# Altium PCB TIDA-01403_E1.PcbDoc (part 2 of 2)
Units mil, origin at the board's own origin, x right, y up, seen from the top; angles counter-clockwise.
Board outline 4150 x 3450 mil, 4 copper layers (Top Layer, GND, PWR, Bottom Layer), stack 61.6 mil thick; 155 components, 99 nets, 498 pads, 229 vias.
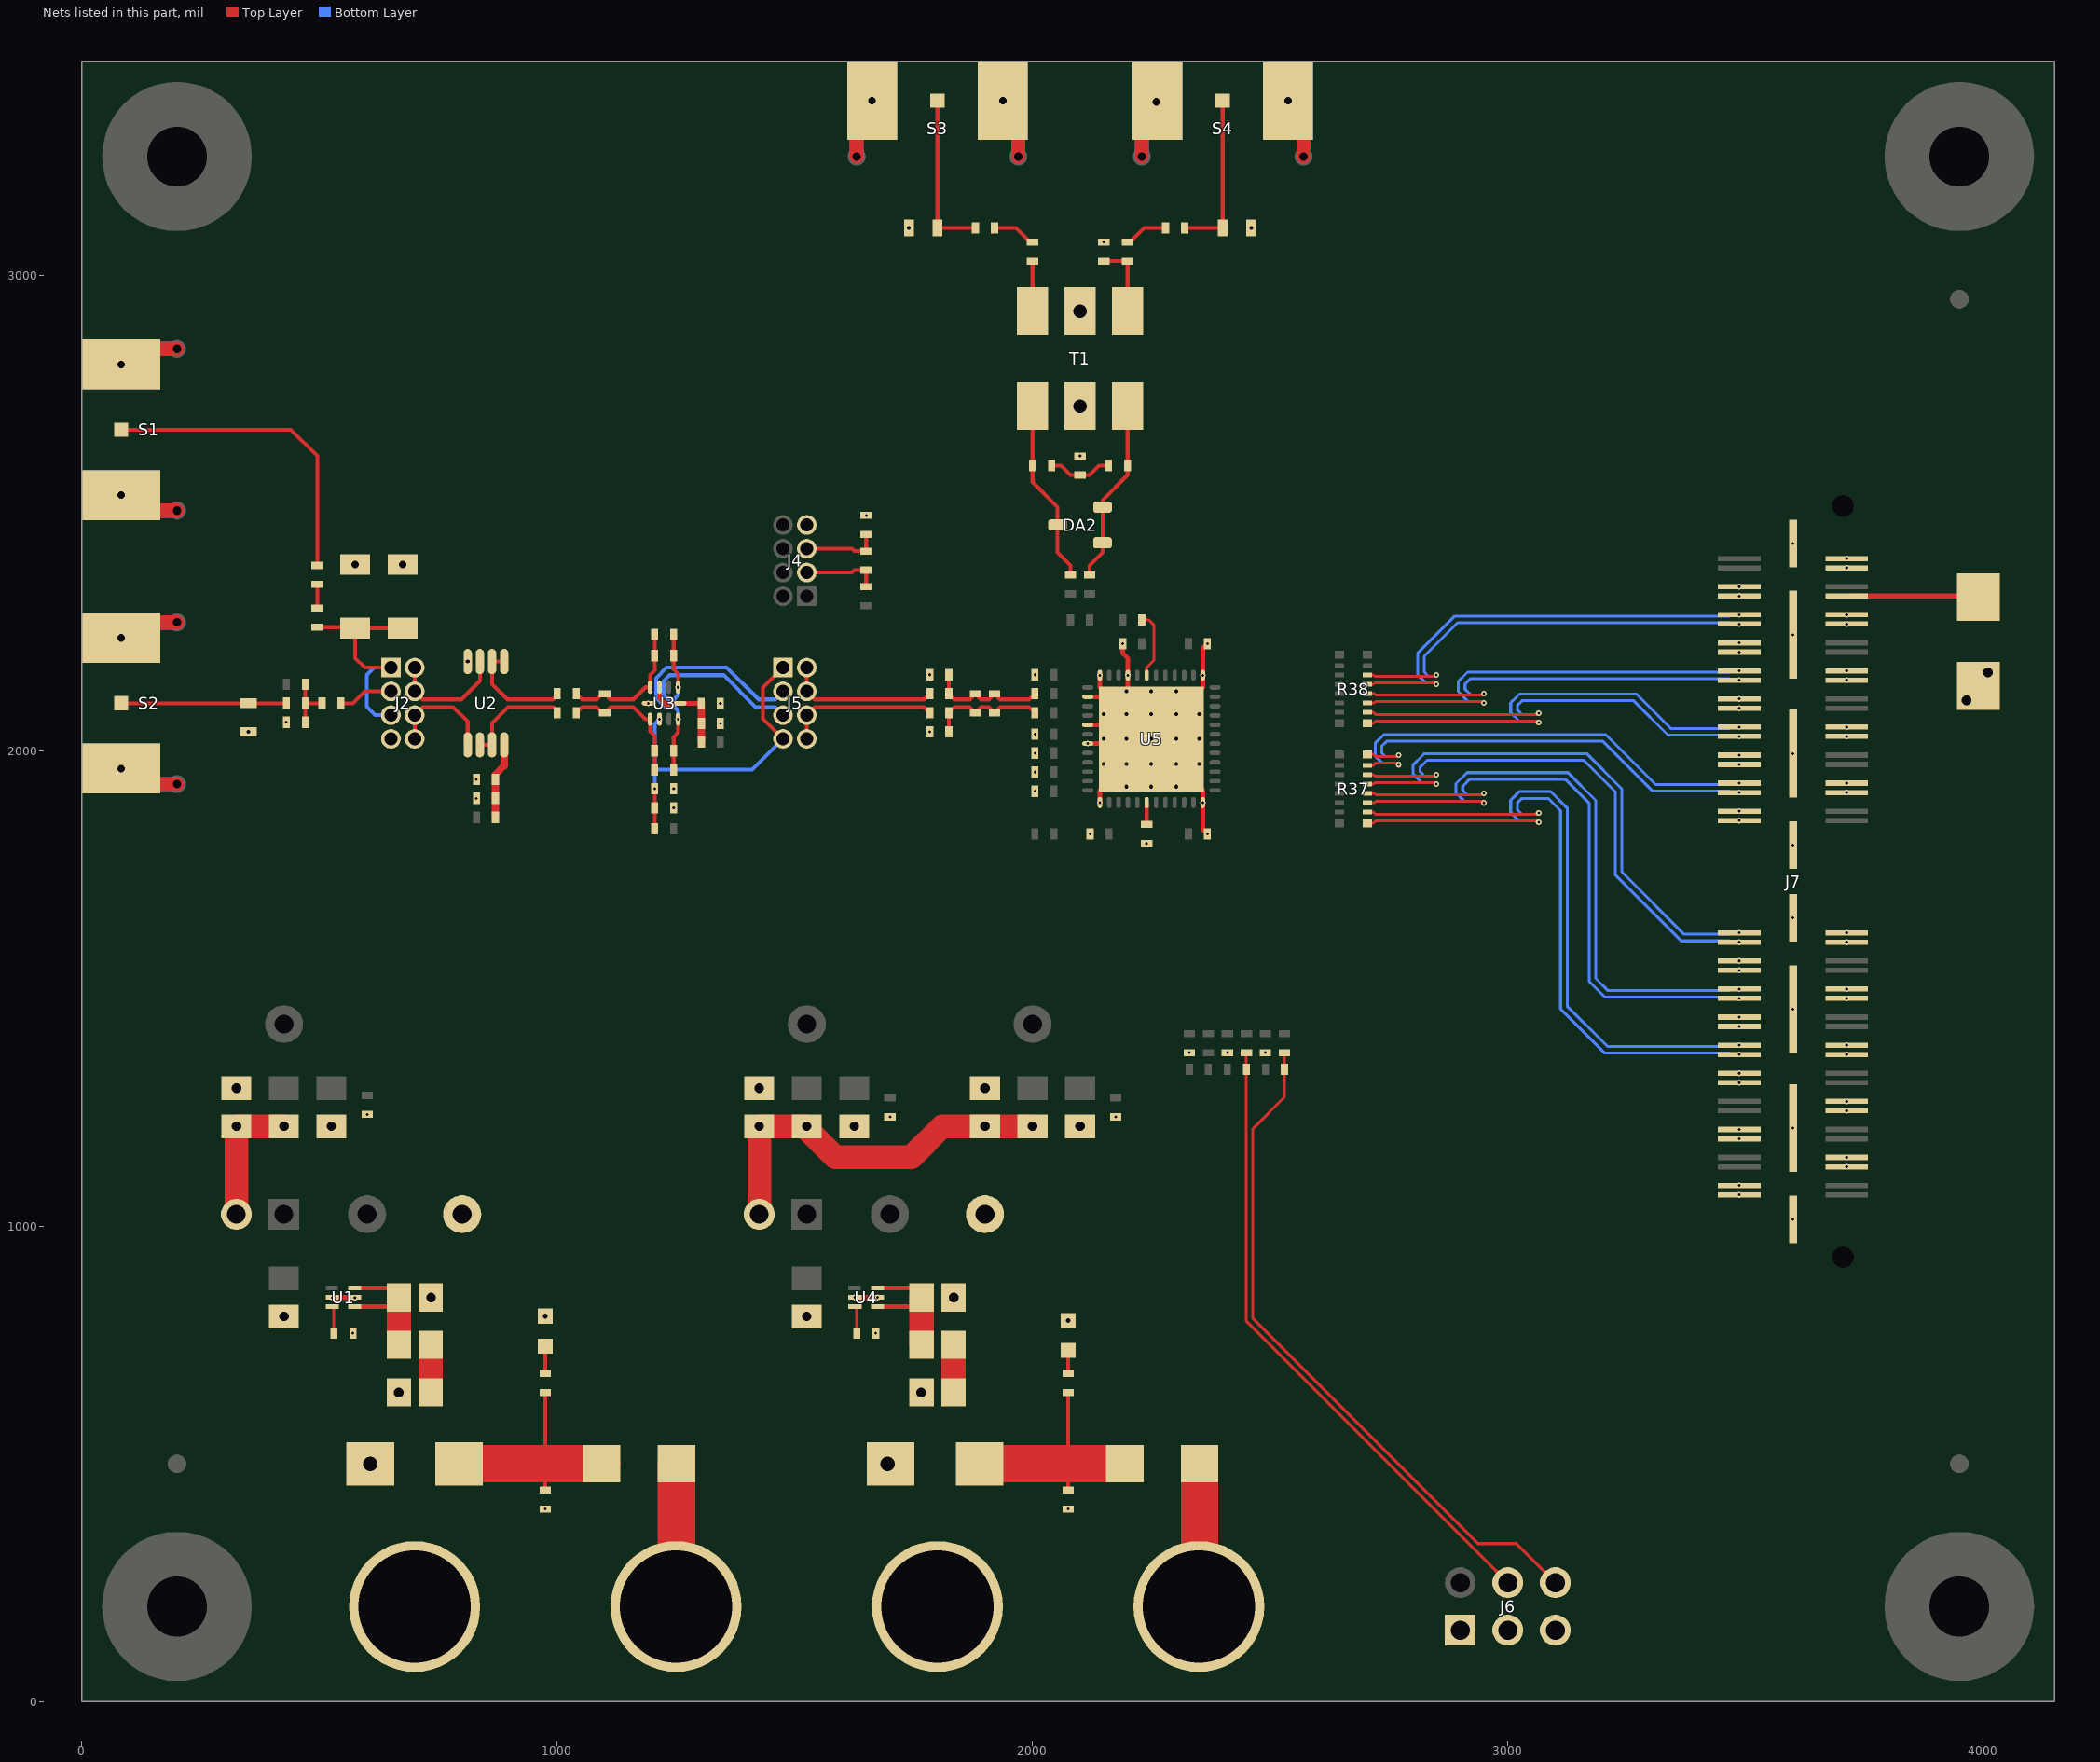
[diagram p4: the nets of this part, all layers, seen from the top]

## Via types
v1: diameter 12, hole 6, Top Layer to Bottom Layer, 153 vias
v2: diameter 40, hole 20, Top Layer to Bottom Layer, 35 vias
v3: diameter 19.68, hole 7.87, Top Layer to Bottom Layer, 21 vias
v4: diameter 32, hole 16, Top Layer to Bottom Layer, 10 vias
v5: diameter 16, hole 8, Top Layer to Bottom Layer, 4 vias
v6: diameter 56, hole 28, Top Layer to Bottom Layer, 2 vias
v7: diameter 60, hole 30, Top Layer to Bottom Layer, 2 vias
v8: diameter 20, hole 10, Top Layer to Bottom Layer, 2 vias

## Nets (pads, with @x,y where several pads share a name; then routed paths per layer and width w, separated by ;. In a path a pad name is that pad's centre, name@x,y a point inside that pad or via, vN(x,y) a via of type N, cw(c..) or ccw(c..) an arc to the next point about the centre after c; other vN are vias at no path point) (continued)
D0_D1_N: J7.57 R37.9 | length 1413
  Top Layer w6: R37.9@2704.53,1847.66 2717.37,1847.66 2721.94,1852.22 3062,1852.22 v1(3065,1849.22)
  Bottom Layer w6: v1(3065,1849.22) 3062,1852.22 3024.2,1852.22 3006,1870.42 3006,1896 3024,1914 3090.8,1914 3125,1879.8 3125,1462.83 3210,1377.83 3372,1377.83 3465.66,1377.83 3468.5,1380.67 v1(3487.01,1380.67)
D0_D1_P: J7.59 R37.10 | length 1366.6
  Top Layer w6: R37.10@2704.53,1870.79 2717.37,1870.79 2721.93,1866.22 3062,1866.22 v1(3065,1869.22)
  Bottom Layer w6: v1(3065,1869.22) 3062,1866.22 3030,1866.22 3020,1876.22 3020,1890.2 3029.8,1900 3085,1900 3111,1874 3111,1457.03 3204.2,1363.83 3465.66,1363.83 3468.5,1360.98 v1(3487.01,1360.98)
D2_D3_N: J7.49 R37.11 | length 1349.1
  Top Layer w6: R37.11@2706.48,1890.47 2719.32,1890.47 2722.16,1893.32 2947,1893.32 v1(2950,1890.32)
  Bottom Layer w6: v1(2950,1890.32) 2947,1893.32 2909.2,1893.32 2891,1911.52 2891,1930.8 2914.2,1954 3126.8,1954 3185,1895.8 3185,1520.94 3210,1495.94 3372,1495.94 3465.66,1495.94 3468.5,1498.78 v1(3487.01,1498.78)
D2_D3_P: J7.51 R37.12 | length 1302.7
  Top Layer w6: R37.12@2706.48,1910.16 2719.32,1910.16 2722.16,1907.32 2947,1907.32 v1(2950,1910.32)
  Bottom Layer w6: v1(2950,1910.32) 2947,1907.32 2915,1907.32 2905,1917.32 2905,1925 2920,1940 3121,1940 3171,1890 3171,1515.14 3204.2,1481.94 3465.66,1481.94 3468.5,1479.09 v1(3487.01,1479.09)
D4_D5_N: J7.41 R37.13 | length 1182.3
  Top Layer w6: R37.13@2704.53,1929.84 2717.37,1929.84 2720.21,1932.68 2847,1932.68 v1(2850,1929.68)
  Bottom Layer w6: v1(2850,1929.68) 2847,1932.68 2819.2,1932.68 2801,1950.89 2801,1970.8 2820.1,1989.9 2824.2,1994 3166,1994 3240,1920 3240,1745 3370.95,1614.05 3465.66,1614.05 3468.5,1616.89 v1(3487.01,1616.89)
D4_D5_P: J7.43 R37.14 | length 1135.9
  Top Layer w6: R37.14@2704.53,1949.53 2717.37,1949.53 2720.21,1946.68 2847,1946.68 v1(2850,1949.68)
  Bottom Layer w6: v1(2850,1949.68) 2847,1946.68 2825,1946.68 2815,1956.68 2815,1965 2830,1980 3160.2,1980 3226,1914.2 3226,1739.2 3365.15,1600.05 3465.66,1600.05 3468.5,1597.2 v1(3487.01,1597.2)
D6_D7_N: J7.33 R37.15 | length 970
  Top Layer w6: R37.15@2704.53,1969.21 2717.37,1969.21 2721.94,1973.78 2767,1973.78 v1(2770,1970.78)
  Bottom Layer w6: v1(2770,1970.78) 2767,1973.78 2736.42,1973.78 2721,1989.2 2721,2015.8 2739.2,2034 3205.8,2034 3310.79,1929.01 3465.66,1929.01 3468.5,1931.85 v1(3487.01,1931.85)
D6_D7_P: J7.35 R37.16 | length 923.7
  Top Layer w6: R37.16@2704.53,1992.34 2717.37,1992.34 2721.93,1987.78 2767,1987.78 v1(2770,1990.78)
  Bottom Layer w6: v1(2770,1990.78) 2767,1987.78 2742.22,1987.78 2735,1995 2735,2010 2745,2020 3200,2020 3304.99,1915.01 3465.66,1915.01 3468.5,1912.17 v1(3487.01,1912.17)
D8_D9_N: J7.25 R38.9 | length 971.3
  Top Layer w6: R38.9@2704.53,2057.66 2717.37,2057.66 2721.94,2062.22 3062,2062.22 v1(3065,2059.22)
  Bottom Layer w6: v1(3065,2059.22) 3062,2062.22 3024.2,2062.22 3006,2080.42 3006,2100.8 3010.1,2104.9 3014.2,2109 3024.3,2119.1 3270.9,2119.1 3342.88,2047.12 3465.66,2047.12 3468.5,2049.96 v1(3487.01,2049.96)
D8_D9_P: J7.27 R38.10 | length 925
  Top Layer w6: R38.10@2704.53,2080.79 2717.37,2080.79 2721.93,2076.22 3062,2076.22 v1(3065,2079.22)
  Bottom Layer w6: v1(3065,2079.22) 3062,2076.22 3030,2076.22 3020,2086.22 3020,2095 3030.1,2105.1 3265.1,2105.1 3337.08,2033.12 3465.66,2033.12 3468.5,2030.28 v1(3487.01,2030.28)
D10_D11_N: J7.17 R38.11 | length 931.9
  Top Layer w6: R38.11@2706.48,2100.47 2719.32,2100.47 2722.16,2103.32 2947,2103.32 v1(2950,2100.32)
  Bottom Layer w6: v1(2950,2100.32) 2947,2103.32 2916.68,2103.32 2896,2124 2896,2146 2915.23,2165.23 3372,2165.23 3465.66,2165.23 3468.5,2168.07 v1(3487.01,2168.07)
D10_D11_P: J7.19 R38.12 | length 885.5
  Top Layer w6: R38.12@2706.48,2120.16 2719.32,2120.16 2722.16,2117.32 2947,2117.32 v1(2950,2120.32)
  Bottom Layer w6: v1(2950,2120.32) 2947,2117.32 2922.48,2117.32 2910,2129.8 2910,2140.2 2921.03,2151.23 3465.66,2151.23 3468.5,2148.39 v1(3487.01,2148.39)
D12_D13_N: J7.9 R38.13 | length 951.8
  Top Layer w6: R38.13@2704.53,2139.84 2717.37,2139.84 2720.21,2142.68 2847,2142.68 v1(2850,2139.68)
  Bottom Layer w6: v1(2850,2139.68) 2847,2142.68 2827.32,2142.68 2810,2160 2810,2204.8 2888.54,2283.34 3465.66,2283.34 3468.5,2286.18 v1(3487.01,2286.18)
D12_D13_P: J7.11 R38.14 | length 905.4
  Top Layer w6: R38.14@2704.53,2159.53 2717.37,2159.53 2720.21,2156.68 2847,2156.68 v1(2850,2159.68)
  Bottom Layer w6: v1(2850,2159.68) 2847,2156.68 2833.11,2156.68 2824,2165.8 2824,2199 2894.34,2269.34 3465.66,2269.34 3468.5,2266.5 v1(3487.01,2266.5)
EXT_VIN1: C7.1 C9.1 C14.1 DA1.1 L3.1 R6.1 | length 604.8
  Top Layer w8: C14.1@975,445 975,500 R6.1@975,650
  Top Layer w51.18: C9.1@733.46,650 L3.1@733.46,750
  Top Layer w78.74: C7.1@793.5,500 975,500 DA1.1@1093.26,500
EXT_VIN2: C28.1 C31.1 C41.1 DA3.1 L7.1 R23.1 | length 604.8
  Top Layer w8: C41.1@2075,445 R23.1@2075,650
  Top Layer w51.18: C31.1@1833.46,650 L7.1@1833.46,750
  Top Layer w78.74: C28.1@1892.76,500 2074.26,500 DA3.1@2192.52,500
FDA_VCC: C20.1 C21.1 L5.2 U3.3 U3.10 | length 197.1
  Top Layer w10: U3.3@1215.16,2133.47 1215.16,2110.58 1225.73,2100 U3.10@1258.47,2100 1302.79,2100 C20.1@1303,2099.79
  Top Layer w15: C20.1@1303,2099.79 1303.16,2099.63 C21.1@1303.16,2057.73 1303.16,2018.08 L5.2@1303.24,2018
FDA_VIN_N: C15.1 C18.2 R7.2 R10.1 U3.6 | length 291.4
  Top Layer w8: R7.2@1040,2080 1052,2092 1083,2092 1095,2080 C15.1@1100,2080 1112,2092 1160,2092 1185.46,2066.54 U3.6@1195.47,2066.54 1195.47,2040.53 1205,2031 C18.2@1205,2000 R10.1@1205,1960
FDA_VIN_P: C15.2 C19.2 R8.2 R11.1 U3.4 | length 287.1
  Top Layer w8: R8.2@1040,2120 1052,2108 1083,2108 1095,2120 C15.2@1100,2120 1112,2108 1160,2108 1185.47,2133.47 U3.4@1195.47,2133.47 ; U3.4@1195,2133.94 U3.4@1195.47,2133.47 ; R11.1@1205,2235 C19.2@1205,2200 1205,2169 1195.47,2159.48 U3.4@1195.47,2133.47
FDA_VOCM: C16.1 C17.1 J5.1 J5.7 R9.1 U3.7 | length 726.6
  Top Layer w8: v1(1205,1920) C16.1@1205,1880 1205,1836.12 R9.1@1205.32,1835.81 ; J5.7@1475,2025 1433.09,2066.91 1433.09,2133.09 J5.1@1475,2175
  Bottom Layer w8: v1(1205,1920) 1205,1960 ; v1(1215.16,2066.54) 1205,2056.38 1205,1960 ; J5.7@1475,2034.87 J5.7@1475,2025 1410,1960 1205,1960
FDAOUT_N: C19.1 J5.5 R11.2 U3.1 | length 479.6
  Top Layer w8: R11.2@1245,2235 C19.1@1245,2200 1245,2171 1254.53,2161.47 v1(1254.53,2133.47)
  Bottom Layer w8: v1(1254.53,2133.47) 1254.53,2117.53 1245,2108 1233.63,2108 1224,2117.63 1224,2146.37 1236.63,2159 1350,2159 1417,2092 1458,2092 J5.5@1475,2075
FDAOUT_P: C18.1 J5.3 R10.2 U3.9 | length 538.8
  Top Layer w8: R10.2@1245,1960 C18.1@1245,2000 1245,2029 1254.53,2038.53 v1(1254.53,2066.54)
  Bottom Layer w8: v1(1254.53,2066.54) 1254.53,2084.47 1247,2092 1227,2092 1208,2111 1208,2153 1230,2175 1356.63,2175 1423.63,2108 1458,2108 J5.3@1475,2125
FILIN_N: J5.6 J5.8 R12.1 | length 321
  Top Layer w8: J5.8@1525,2025 J5.6@1525,2075 1542,2092 1772,2092 R12.1@1784,2080
FILIN_P: J5.2 J5.4 R13.1 | length 321
  Top Layer w8: J5.2@1525,2175 J5.4@1525,2125 1542,2108 1772,2108 R13.1@1784,2120
FILOUT_N: C26.1 C35.2 R12.2 R18.1 R21.1 | length 250.9
  Top Layer w8: C26.1@1824,2040 R12.2@1824,2080 1836,2092 1868.21,2092 R18.1@1880,2080.21 ; R18.1@1879.9,2080.11 R18.1@1880,2080 1892,2092 1908,2092 C35.2@1920,2080 1932,2092 1955,2092 1985,2092 1993,2092 R21.1@2005,2080
FILOUT_P: C27.1 C35.1 R13.2 R18.2 R22.1 | length 250.9
  Top Layer w8: C27.1@1824,2160 R13.2@1824,2120 1836,2108 1868.21,2108 R18.2@1880,2119.79 ; R18.2@1879.9,2119.9 R18.2@1880,2120 1892,2108 1908,2108 C35.1@1920,2120 1932,2108 1940,2108 1968,2108 1993,2108 R22.1@2005,2120
GND: BA1.1 BA3.1 C1.2 C2.2 C4.2 C5.2 C6.1 C7.2 C8.2 C9.2 C10.2 C11.1 C12.2 C13.2 C14.2 C16.2 C17.2 C20.2 C21.2 C22.2 C23.2 C24.2 C25.2 C26.2 C27.2 C28.2 C29.2 C31.2 C32.2 C33.2 C36.2 C37.2 C38.2 C39.2 C40.2 C41.2 C42.2 C44.2 C46.2 C47.2 C48.2 C50.2 C51.2 C52.2 C53.2 C54.2 C55.2 D1.1 D2.1 J2.7 J4.7 J6.1 J6.3 J6.5 J7.2 J7.4 J7.5 J7.7 J7.10 J7.12 J7.13 J7.15 J7.18 J7.20 J7.21 J7.23 J7.26 J7.28 J7.29 J7.31 J7.34 J7.36 J7.37 J7.39 J7.42 J7.44 J7.45 J7.47 J7.50 J7.52 J7.53 J7.55 J7.58 J7.60 J7.61 J7.63 J7.66 J7.68 J7.69 J7.71 J7.74 J7.76 J7.77 J7.79 J7.81 J7.82 J7.83 J7.84 J7.85 J7.86 J7.87 J7.88 R1.1 R2.1 R16.1 R17.1 R25.1 R29.1 R32.1 S1.2 S1.3 S1.4 S1.5 S2.2 S2.3 S2.4 S2.5 S3.2 S3.3 S3.4 S3.5 S4.2 S4.3 S4.4 S4.5 T1.2 T1.5 TP3.1 TP6.1 U1.2 U1.5 U2.4 U3.5 U4.2 U4.5 U5.1 U5.9 U5.12 U5.14 U5.17 U5.19 U5.25 U5.36 U5.49 | length 2940.8
  Top Layer w10: U1.2@526.38,850 U1.5@573.62,850 ; v1(1626.38,850) v1(1673.62,850) ; v1(2116.14,2015.16) U5.49@2240.16,2015.16 ; U5.17@2116.14,2054.53 U5.49@2220.47,2054.53 ; U5.14@2116.14,2113.58 2161.42,2113.58 v3(2197.48,2077.52) U5.49@2200.79,2074.21 ; v1(2141.73,1891.14) U5.49@2141.73,1916.73 ; U5.49@2141.73,2133.27 v1(2141.73,2158.86) ; v1(2190,2225) 2190,2205 2200.79,2194.21 v1(2200.79,2158.86) U5.49@2200.79,2074.21 ; v3(2250,2025) U5.49@2220.47,2054.53 ; U5.49@2358.27,1916.73 v1(2358.27,1891.14) 2358.27,1834.73 v1(2368,1825) ; U5.49@2358.27,2133.27 v1(2358.27,2158.86) 2358.27,2215.27 v1(2368,2225) ; U5.49@2200.79,2074.21 U5.49@2220.47,2054.53
  Top Layer w30: v4(82.5,1962.5) 115,1930 200,1930 ; v4(82.5,2237.5) 115,2270 200,2270 ; v4(82.5,2537.78) 115,2505.28 200,2505.28 ; v4(82.5,2812.78) 115,2845.28 200,2845.28 ; 1630,3250 1630,3335 v4(1662.5,3367.5) ; v4(1937.5,3367.5) 1970,3335 1970,3250 ; 2230,3250 2230,3335 S4.2@2262.5,3367.5 ; v4(2537.5,3367.5) 2570,3335 2570,3250
  Bottom Layer w30: v4(82.5,1962.5) 115,1930 200,1930 ; v4(82.5,2237.5) 115,2270 200,2270 ; v4(82.5,2812.78) 115,2845.28 200,2845.28 ; S1.4@115,2505.28 200,2505.28 ; 1630,3250 1630,3335 v4(1662.5,3367.5) ; v4(1937.5,3367.5) 1970,3335 1970,3250 ; 2230,3250 2230,3335 S4.4@2262.5,3367.5 ; v4(2537.5,3367.5) 2570,3335 2570,3250
  other v1: 975,405 2075,405 570,775 1670,775 526.97,849.68 574.21,849.68 3600,1014.13 3487.01,1065.71 3487.01,1085.39 3712.99,1124.76 3712.99,1144.45 3487.01,1183.82 3487.01,1203.5 3600,1206.26 1700,1230 2175,1230 600,1235 3712.99,1242.87 3712.99,1262.56 3487.01,1301.93 3487.01,1321.61 3712.99,1360.98 2330,1365 2410,1365 2490,1365 3712.99,1380.67 3487.01,1420.04 3487.01,1439.72 3600,1456.26 3712.99,1479.09 3712.99,1498.78 3487.01,1538.15 3487.01,1557.83 3712.99,1597.2 3712.99,1616.89 3600,1648.78 3600,1801.54 2240,1805 2121,1825 3487.01,1853.11 3487.01,1872.8 1245,1880 830,1900 3712.99,1912.17 2005,1915 1245,1920 3712.99,1931.85 830,1940 2005,1955 3487.01,1971.22 3487.01,1990.91 3600,1993.76 2005,1995 3712.99,2030.28 2005,2035 1784,2040 3712.99,2049.96 1343.16,2057.73 430,2060 3487.01,2089.33 1191.54,2100 1343,2099.79 3487.01,2109.02 3712.99,2148.39 1784,2160 2005,2160 3712.99,2168.07 3487.01,2207.44 3487.01,2227.13 3600,2244.06 3712.99,2266.5 3712.99,2286.18 3487.01,2325.55 3487.01,2345.24 3712.99,2384.61 3712.99,2404.29 3600,2436.18 1650,2495 2100,2620 2150,3070
  other v2: 666.54,650 1765.55,650 425,810 1525,810 734.45,850 1834.45,850 525,1210 1625,1210 2100,1210 325,1290 1425,1290 1900,1290 3965,2105.98 4010,2165
  other v3: 2197.48,1924.61 2250,1924.61 2302.52,1924.61 2149.61,1972.48 2197.48,1972.48 2250,1972.48 2302.52,1972.48 2350.39,1972.48 2149.61,2025 2197.48,2025 2302.52,2025 2350.39,2025 2149.61,2077.52 2250,2077.52 2302.52,2077.52 2350.39,2077.52 2197.48,2125.39 2250,2125.39 2302.52,2125.39
  other v4: 575,2391.95 675,2391.95 2260,3365
  other v5: 350,2040 811.62,2187.6 1740,3100 2460,3100
  other v6: 2100,2725 2100,2925
  other v7: 606.5,500 1695,500
  other v8: 2075,801.5 975,810.74
NetBA2_1: BA2.1 DA1.2 | length 299.3
  Top Layer w78.74: BA2.1@1250.74,200.74 DA1.2@1250.74,500
NetBA4_1: BA4.1 DA3.2 | length 298.3
  Top Layer w78.74: BA4.1@2351.74,201.74 DA3.2@2351.74,500
NetC1_1: C1.1 J1.2 L1.1 | length 285
  Top Layer w50: J1.2@325,1025 v2(325,1210) v2(425,1210)
NetC3_1: C3.1 R2.2 R3.1 R5.1 | length 115
  Top Layer w8: R2.2@470,2060 C3.1@470,2100 ; R3.1@470,2140 C3.1@470,2100 ; R5.1@505,2100 C3.1@470,2100
NetC5_1: C5.1 U1.3 | length 56.8
  Top Layer w6: U1.3@526.38,830.32 530,826.69 C5.1@530,775
NetC6_2: C6.2 C11.2 J2.1 J2.5 R4.2 | length 509.2
  Top Layer w8: R4.2@495,2260 573.07,2260 C6.2@575,2258.07 ; J2.1@650,2175 595,2175 575,2195 C6.2@575,2258.07 ; C11.2@675,2258.07 C6.2@575,2258.07
  Bottom Layer w8: J2.5@650,2075 617,2075 599,2093 599,2159 615,2175 J2.1@650,2175
NetC22_1: C22.1 C33.1 J3.2 L6.1 L10.1 | length 816.8
  Top Layer w50: J3.2@1425,1025 v2(1425,1210) v2(1525,1210) 1525,1205 1585,1145 1745,1145 1810,1210 v2(1900,1210) v2(2000,1210)
NetC25_1: C25.1 U4.3 | length 56.8
  Top Layer w6: U4.3@1626.38,830.32 1630,826.69 C25.1@1630,775
NetC34_1: C34.1 R19.1 | length 92.4
  Top Layer w8: C34.1@1920,3100 1965,3100 1995,3070 R19.1@2000,3070
NetC34_2: C34.2 R17.2 S3.1 | length 347.5
  Top Layer w8: S3.1@1800,3367.5 R17.2@1800,3100 C34.2@1880,3100
NetC43_2: C43.2 DA2.3 R20.1 T1.4 | length 388.5
  Top Layer w8: T1.4@2000,2725 R20.1@2000,2600 2000,2565 2052.76,2512.24 DA2.3@2052.76,2475 2052.36,2474.6 2052.36,2417.64 2080,2390 C43.2@2080,2370
NetC44_1: C44.1 R20.2 R26.1 | length 126.6
  Top Layer w8: R20.2@2045,2600 2060,2600 2080,2580 2120,2580 2140,2600 R26.1@2155,2600
NetC45_2: C45.2 DA2.1 DA2.2 R26.2 T1.6 | length 388.1
  Top Layer w8: C45.2@2120,2370 2120,2390 2147.24,2417.24 DA2.1@2147.24,2437.6 DA2.2@2147.24,2512.4 2147.24,2527.24 2200,2580 R26.2@2200,2600 T1.6@2200,2725
NetC49_1: C49.1 R27.1 | length 92.4
  Top Layer w8: R27.1@2200,3070 2205,3070 2235,3100 C49.1@2280,3100
NetC49_2: C49.2 R32.2 S4.1 | length 347.5
  Top Layer w8: C49.2@2320,3100 R32.2@2400,3100 S4.1@2400,3367.5
NetC55_1: C55.1 J7.8 | length 267.9
  Top Layer w10: C55.1@3987.95,2325.55 C55.1@3990,2323.5
  Top Layer w11.02: J7.8@3722.99,2325.55 C55.1@3987.95,2325.55
NetD1_2: D1.2 R6.2 | length 60.7
  Top Layer w8: R6.2@975,690 D1.2@975,747.74 D1.2@975,750.7
NetD2_2: D2.2 R23.2 | length 48.5
  Top Layer w8: R23.2@2075,690 D2.2@2075,738.5
NetJ2_3: J2.3 R5.2 | length 115.4
  Top Layer w8: R5.2@545,2100 570,2100 595,2125 J2.3@650,2125
NetJ4_3: J4.3 R14.1 R15.2 | length 162.1
  Top Layer w8: J4.3@1525,2375 1620,2375 1625,2380 R15.2@1650,2380 R14.1@1650,2345
NetJ4_5: J4.5 R15.1 R16.2 | length 162.1
  Top Layer w8: J4.5@1525,2425 1620,2425 1625,2420 R15.1@1650,2420 R16.2@1650,2455
NetL2_2: L2.2 R4.1 | length 50
  Top Layer w8: R4.1@495,2300 L2.2@495,2350
NetR19_2: R19.2 T1.3 | length 105
  Top Layer w8: T1.3@2000,2925 R19.2@2000,3030
NetR25_2: R25.2 R27.2 T1.1 | length 155
  Top Layer w8: R25.2@2150,3030 R27.2@2200,3030 T1.1@2200,2925
NetR28_1: R28.1 U5.7 | length 141.4
  Top Layer w6: R28.1@2230,2275 2245,2275 2255,2265 2255,2190 2240.16,2175.16 U5.7@2240.16,2158.86
OPA_VCC: C12.1 C13.1 L4.2 U2.8 | length 160
  Top Layer w15: L4.2@870,1860 C12.1@870,1900 C13.1@870,1940 870,1950 888.39,1968.39 U2.8@888.39,2012.4
OPAIN_N: J2.6 J2.8 U2.5 | length 236
  Top Layer w8: J2.8@700,2025 J2.6@700,2075 717,2092 781,2092 811.61,2061.39 U2.5@811.61,2012.4 U2.5@807.61,2016.4
OPAIN_P: J2.2 J2.4 U2.3 | length 250.9
  Top Layer w8: J2.2@700,2175 J2.4@700,2125 717,2108 798,2108 837.21,2147.21 U2.3@837.21,2187.6
OPAOUT_N: R7.1 U2.6 U2.7 | length 230.3
  Top Layer w8: U2.6@837.21,2012.4 U2.7@862.8,2012.4 862.8,2058.8 896,2092 992,2092 1000,2084 R7.1@1000,2080
OPAOUT_P: R8.1 U2.1 U2.2 | length 230.3
  Top Layer w8: U2.1@888.39,2187.6 U2.2@862.8,2187.6 862.8,2140.21 895,2108 991,2108 1000,2117 R8.1@1000,2120
RESET: R29.2 U5.30 | length 46.2
  Top Layer w8: R29.2@2240,1845 2240.16,1845.16 U5.30@2240.16,1891.14
SCLK_IN: J6.6 R35.1 R36.2 | length 1453.3
  Top Layer w6: R36.2@2530,1365 R35.1@2530,1330 2530,1271.3 2463.7,1205 2463.7,805.67 2937.19,332.19 3017.81,332.19 J6.6@3100,250
SDI_IN: J6.4 R33.1 R34.2 | length 1342.8
  Top Layer w6: R34.2@2450,1365 R33.1@2450,1330 2450,800 J6.4@3000,250
SIGNAL_IN: C3.2 R1.2 S2.1 | length 347.5
  Top Layer w8: S2.1@82.5,2100 R1.2@350,2100 C3.2@430,2100
V_OFFSET: L2.1 S1.1 | length 665.4
  Top Layer w8: S1.1@82.5,2675.28 439.72,2675.28 495,2620 L2.1@495,2390
VIN1: C10.1 L3.2 U1.4 U1.6 | length 274.3
  Top Layer w9.84: U1.4@573.62,830.32 646.85,830.32 C10.1@666.54,850 ; U1.6@573.62,869.68 C10.1@646.85,869.68
  Top Layer w51.18: L3.2@666.54,750 C10.1@666.54,850
VIN2: C32.1 L7.2 U4.4 U4.6 | length 302.1
  Top Layer w9.84: U4.4@1673.62,830.32 1746.85,830.32 C32.1@1766.54,850 1746.85,869.68 U4.6@1673.62,869.68
  Top Layer w51.18: L7.2@1766.54,750 C32.1@1766.54,850
pads on no net: FID1.1 FID2.1 FID3.1 H1.1 H2.1 H3.1 H4.1 J7.14 J7.16 J7.22 J7.24 J7.30 J7.32 J7.38 J7.40 J7.46 J7.48 J7.54 J7.56 J7.62 J7.64 J7.65 J7.67 J7.70 J7.72 J7.73 J7.75 J7.78 J7.80 J7.MH1 J7.MH2 S1. S2. S3. S4. SH-J1.0 SH-J2.0 U3.2 U3.8 U5.21 U5.23 U5.31 U5.32

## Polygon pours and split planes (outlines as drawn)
+5V0_OUT on Top Layer "TOP_LAYER_+5V0_OUT_P158" (solid, remove dead copper, pour order 158): 390,935 390,865 537.44,865 540.16,867.72 540,930 535,935
+1V8_OUT on Top Layer "TOP_LAYER_+1V8_OUT_P156" (solid, remove dead copper, pour order 156): 1490,935 1490,865 1637.44,865 1640.16,867.72 1640,930 1635,935
+5V0A on Top Layer "h" (solid, remove dead copper, pour order 42): 385,1260 380,1265 380,1465 385,1470 620,1470 625,1465 625,1265 620,1260
EXT_VIN1 on Top Layer "Top Layer-No Net 1" (solid, pour order 110): 707,780 707,488 740,455 745,450 955,450 960,445 960,435 990,435 990,445 995,450 1130,450 1135,455 1135,545 1130,550 850,550 830,550 760,620 760,780
VIN1 on Top Layer "Top Layer-No Net 2" (solid, pour order 114): 640,720 640,815 635,820 559.97,820 560.07,880 693,880 693,720
EXT_VIN2 on Top Layer "Top Layer-No Net 1" (solid, pour order 116): 1808,780 1808,488 1841,455 1846,450 2056,450 2061,445 2061,435 2091,435 2091,445 2096,450 2231,450 2236,455 2236,545 2231,550 1951,550 1931,550 1861,620 1861,780
VIN2 on Top Layer "Top Layer-No Net 2" (solid, pour order 118): 1740,720 1740,815 1735,820 1659.95,820 1660.05,880 1793,880 1793,720
+1V8A on Top Layer "h" (solid, remove dead copper, pour order 120): 1485,1260 1480,1265 1480,1465 1485,1470 1720,1470 1725,1465 1725,1265 1720,1260
ADC_DVDD on Top Layer "h" (solid, remove dead copper, pour order 122): 1960,1260 1955,1265 1955,1465 1960,1470 2195,1470 2200,1465 2200,1265 2195,1260
GND on Top Layer "Top Layer-No Net" (solid, remove dead copper, pour order 160): 0,0 4150,0 4150,3450 0,3450 0,0
GND on GND "Signal Layer 1-No Net 1" (solid, remove dead copper, pour order 142): 3075,50 4100,50 4100,3400 50,3400 50,50
ADC_DVDD on PWR "PWR-No Net 2" (solid, remove dead copper, pour order 20): 2180,2290 2310,2290 2315,2285 2315,2265 2315,2251.41 2310,2246.41 2183.59,2246.41 2180,2250 2180,2255
GND on PWR "PWR-No Net 2" (solid, remove dead copper, pour order 18): 1450,3400 4100,3400 4100,50 50,50 50,1225 2510,1225 2525,1240 2525,1265 2525,2300 2510,2315 2450,2315 2140,2315 2125,2300 2125,2075 2105,2075 2015,2075 2010,2070 2010,2050 2010,1920 2000,1910 1955,1910 1435,1910 1420,1925 1420,3375 1445,3400
+5V0A on PWR "Signal Layer 2-No Net 3" (solid, pour order 130): 65,1260 1395,1260 1400,1265 1400,3400 50,3400 50,1275
+1V8A on PWR "Signal Layer 2-No Net 4" (solid, remove dead copper, pour order 132): 1399.97,1265 1404.97,1260 1840,1260 1850,1270 1850,1750 2015,1750 2020,1755 2020,1895 2015,1900 1399.97,1900
ADC_AVDD on PWR "PWR-No Net 1" (solid, remove dead copper, pour order 166): 2020,1755 2020,2050 2025,2055 2130,2055 2135,2060 2135,2140 2140,2145 2245,2145 2250,2140 2250,1910 2235,1895 2235,1755 2230,1750 2025,1750
ADC_DVDD on PWR "PWR-No Net" (solid, remove dead copper, pour order 170): 1860,1260 1850,1270 1850,1750 2230,1750 2275,1750 2275,2290 2500,2290 2500,1265 2495,1260
GND on Bottom Layer "Bottom Layer-No Net" (solid, remove dead copper, pour order 162): 0,0 4150,0 4150,3450 0,3450 0,0

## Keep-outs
Keep-Out Layer:
  circle w4: c3705.12,934.76 r30
  circle w4: c3705.12,2514.92 r30
  lines w8: 25,25 25,3425 4125,3425 4125,25 25,25
  text ".Layer_Name" at 582,-848.49 h60

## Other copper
Top Layer:
  text ".Layer_Name" at 582,-848.49 h60
GND:
  text "GND" at 582,-848.49 h60
PWR:
  text ".Layer_Name" at 595,-850 h60
Bottom Layer:
  text ".Layer_Name" at 582,-848.49 h60

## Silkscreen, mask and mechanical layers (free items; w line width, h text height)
Top Overlay:
  region: 1100,2800 800,2800 800,2700 1100,2700
  lines w6: 385,2140 385,2125 390,2120 410,2100 ; 1850,2385 1840,2375 1840,2275 1870,2245 1940,2245 1960,2245 2005,2200 2005,2190 ; 2043,2554 2057,2554 2077,2574
  lines w8: 1000,2598 1550,2598
  lines w10: 3320,2790 3350,2790
  text "CLKIN_P" at 1540,3190 h30 r90
  text "CLKIN_N" at 2705,3175 h30 r90
  text "V_OFFSET" at 85,2950 h30
  text ".PRJ_Number" at 2825,2765 h50
  text ".PCB_Rev" at 3385,2765 h50
  text "DATA FORMAT SELECTION:" at 1000,2623 h30
  text "2's COMP, LVDS" at 1005,2460 h30
  text "2's COMP, CMOS" at 1010,2410 h30
  text "CLKOUT_P" at 3185,2405 h30
  text "OFF. BINARY, CMOS" at 920,2360 h30
  text "CLKOUT_N" at 3185,2355 h30
  text "OFF. BINARY, LVDS" at 925,2305 h30
  text "D12_D13_N" at 3170,2285 h30
  text "D12_D13_P" at 3170,2235 h30
  text "D10_D11_N" at 3175,2165 h30
  text "D10_D11_P" at 3175,2115 h30
  text "D8_D9_N" at 3215,2050 h30
  text "D8_D9_P" at 3215,2000 h30
  text "D6_D7_N" at 3215,1930 h30
  text "D6_D7_P" at 3215,1880 h30
  text "SIGNAL_IN" at 75,1800 h30
  text "D4_D5_N" at 3220,1620 h30
  text "D4_D5_P" at 3220,1570 h30
  text "+1V8A" at 1470,1550 h30
  text "+1V8D" at 1945,1550 h30
  text "+5V0A" at 365,1545 h30
  text "D2_D3_N" at 3220,1500 h30
  text "D2_D3_P" at 3220,1450 h30
  text "D0_D1_N" at 3225,1385 h30
  text "D0_D1_P" at 3225,1335 h30
  text "SEN_IN" at 2910,340 h30 r90
  text "SDI_IN" at 3010,340 h30 r90
  text "SCLK_IN" at 3110,340 h30 r90
  text ".Layer_Name" at 582,-848.49 h60
Bottom Overlay:
  text ".Layer_Name" at 582,-848.49 h60
Top Paste:
  text ".Layer_Name" at 577,-858.49 h60
Bottom Paste:
  text ".Layer_Name" at 582,-848.49 h60
Top Solder:
  text ".Layer_Name" at 577,-858.49 h60
  text ".Layer_Name" at 577,-858.49 h60
Bottom Solder:
  text ".Layer_Name" at 582,-848.49 h60
M1 Board Outline:
  the board outline again, w10
M2 Board Dimensions:
  rectangle: 125,-400 500,-275
  rectangle: 0,-275 125,-150
  lines w7: 0,-275 1000,-275 ; 125,-400 125,-150 ; 250,-400 250,-150 ; 500,-400 500,-150 ; 750,-400 750,-150 ; 0,-400 0,-150 1000,-150 1000,-400 0,-400
M3 3D STEP Top:
  text ".Layer_Name" at 577,-858.49 h60
M4 3D STEP Bottom:
  text ".Layer_Name" at 577,-858.49 h60
M5 Assembly Top:
  circle w10: c2167,2437 r8.54
  circle w10: c2627,2192 r7.07
  circle w10: c2627,1991 r8.06
  circle w10: c1476,2477 r13.34
  circle w10: c1475,2175 r13.34
  circle w10: c649,2175 r13.93
  circle w10: c3415,2405 r8.06
  circle w10: c1525,1027 r18.03
  circle w10: c424,1026 r14.04
  lines w10: -292,-930.17 6308,-930.17 ; -292,-726.83 6310,-726.83 ; -292,-523.5 -292,-1133.5 3713,-1133.5 6310,-1133.5 6310,-523.5 -291.5,-523.5 -291.5,-1133.5 1284,-1133.5 ; 2173,-1133.5 2173,-523.5 ; 3440,-726.83 3440,-523.5 ; 4280,-726.83 4280,-523.5 ; 4902,-1140 4902,-937.17
  text "COMPONENTS MARKED 'DNP' SHOULD NOT BE POPULATED." at 1153.5,-318.5 h25
  text "ASSEMBLY VARIANT:" at 1153,-434 h25
  text ".VariantName" at 2189,-434 h25
  text "PCB VIEWED FROM TOP SIDE" at -228.5,-655.67 h25
  text "BOARD #:" at 2248,-655.67 h25
  text ".PRJ_Number" at 2793.5,-655.67 h25
  text "REV:" at 3638,-655.67 h25
  text ".PCB_Rev" at 3929.5,-655.67 h25
  text "SVN REV:" at 4476,-655.67 h25
  text ".VersionControl_RevNumber" at 4982,-655.67 h25
  text ".Layer_Name" at 582,-848.49 h60
  text "TID #:" at 2248,-859 h25
  text ".TID" at 2793.5,-859 h25
  text "PLOT NAME =" at -228.5,-1064.34 h25
  text ".plot_File_Name" at 577,-1064.34 h25
  text "GENERATED    :" at 2250,-1064.34 h25
  text ".Print_Date" at 3119.5,-1064.34 h25
  text ".Print_Time" at 3848.5,-1064.34 h25
  text "TEXAS INSTRUMENTS" at 5113,-1064.34 h25
M6 Assembly Bottom:
  lines w10: -292.5,-727.33 6309.5,-727.33 ; -290.5,-930.67 6309.5,-930.67 ; 1115.5,-1140.5 1115.5,-937.67 ; 1737.5,-727.33 1737.5,-524 ; 2577.5,-727.33 2577.5,-524 ; 3844.5,-1134 3844.5,-524 ; 4733.5,-1134 6309,-1134 6309,-524 -292.5,-524 -292.5,-1134 2304.5,-1134 6309.5,-1134 6309.5,-524
  text "COMPONENTS MARKED 'DNP' SHOULD NOT BE POPULATED." at 6102,-318 h30
  text ".VariantName" at 5058,-434 h30
  text "ASSEMBLY VARIANT:" at 6097,-434 h30
  text ".VersionControl_RevNumber" at 1035.5,-656.17 h30
  text "SVN REV:" at 1541.5,-656.17 h30
  text ".PCB_Rev" at 2088,-656.17 h30
  text "REV:" at 2379.5,-656.17 h30
  text ".PRJ_Number" at 3224,-656.17 h30
  text "BOARD #:" at 3769.5,-656.17 h30
  text "PCB VIEWED FROM BOTTOM SIDE" at 6246,-656.17 h30
  text ".TID" at 3224,-859.5 h30
  text "TID #:" at 3769.5,-859.5 h30
  text ".Layer_Name" at 5515,-865 h60
  text "TEXAS INSTRUMENTS" at 904.5,-1064.84 h30
  text ".Print_Time" at 2169,-1064.84 h30
  text ".Print_Date" at 2898,-1064.84 h30
  text "GENERATED    :" at 3767.5,-1064.84 h30
  text ".plot_File_Name" at 5440.5,-1064.84 h30
  text "PLOT NAME =" at 6246,-1064.84 h30
M9 Title Sheet:
  drawing of 57 lines, arcs and shapes, not listed
  text "1" at 739.84,8036.5 h70
  text "2" at 3235.5,8036.5 h70
  text "3" at 5724.84,8036.5 h70
  text "4" at 8231.51,8036.5 h70
  text "5" at 10730.5,8036.5 h70
  text "6" at 13235.5,8036.5 h70
  text "A" at -416.5,6893.5 h70
  text "A" at 14383.5,6893.5 h70
  text "B" at -416.5,4513.5 h70
  text "B" at 14383.5,4513.5 h70
  text "C" at -416.5,2138.5 h70
  text "C" at 14383.5,2138.5 h70
  text "PROJECT TITLE:" at 11343.5,277.5 h45
  text ".PRJ_Title" at 11393.5,144.17 h70
  text "DESIGNED FOR:" at 11343.5,-23.5 h45
  text ".PRJ_Customer" at 11393.5,-163.5 h70
  text "D" at -416.5,-231.5 h70
  text "D" at 14383.5,-231.5 h70
  text "FILE NAME:" at 11343.5,-323.5 h45
  text ".PCB_File_Name_No_Path" at 11393.5,-443.5 h70
  text "Texas Instruments (TI) and/or its licensors do not warrant the accuracy or completeness of this specification" at 6374,-605.34 h45
  text "ENGINEER:" at 11343.5,-613.5 h45
  text "LAYOUT BY:" at 12848.5,-613.5 h45
  text "or any information contained therein. TI and/or its licensors do not warrant that this design will meet" at 6329.01,-718 h45
  text ".PRJ_Engineer" at 11393.5,-768.49 h70
  text ".PCB_Layout" at 12899,-768.49 h70
  text "the specifications, will be suitable for your application or fit for any particular purpose, or will operate in" at 6329.01,-830.67 h45
  text "ALTIUM DESIGNER VERSION:" at 12848.5,-923.5 h45
  text "an implementation. TI and/or its licensors do not warrant that the design is production worthy. You should" at 6329.01,-943.33 h45
  text "completely validate and test your design implementation to confirm the system functionality for your application." at 6374,-1056 h45
  text ".print_Scale" at 11393.5,-1056.83 h70
  text ".Application_BuildNumber" at 12899,-1056.83 h70
  text "1" at 739.84,-1263.5 h70
  text "2" at 3235.5,-1263.5 h70
  text "3" at 5724.84,-1263.5 h70
  text "4" at 8231.51,-1263.5 h70
  text "5" at 10730.5,-1263.5 h70
  text "6" at 13235.5,-1263.5 h70
M10 Fab Notes:
  drawing of 189 lines, arcs and shapes, not listed
  text "DESIGN INFORMATION" at 12378.02,6201 h60
  text "MIN. TRACK WIDTH:" at 11733.46,6021 h60
  text "6" at 12829.7,6021 h60
  text "MIL" at 12990,6020 h60
  text "MIL" at 12990,5897 h60
  text "7.65" at 12743,5894 h60
  text "MIN. CLEARANCE:" at 11733.46,5889 h60
  text "MIN. VIA PAD SIZE:" at 11733.46,5757 h60
  text "12" at 12799.71,5757 h60
  text "MIL" at 12989,5756 h60
  text "0.05mm (2MIL)" at 12428.46,5615.29 h60
  text "MINIMUM ANNULAR RING" at 11404.23,5611 h60
  text "EXTERNAL" at 13136.46,5611 h60
  text "PER" at 11604.23,5493 h60
  text "IPC-D-275 CLASS 2 LEVEL C" at 11824.23,5493 h60
  text "MIL, HOLES" at 13312.46,5380.71 h60
  text "+/-" at 12920,5380 h60
  text "+/-" at 13774,5380 h60
  text "REGISTRATION TOLERANCES:" at 11404.23,5375 h60
  text "METAL" at 12604,5375 h60
  text "5" at 13180.2,5375 h60
  text "3" at 14013.2,5375 h60
  text "MIL" at 14129.46,5375 h60
  text "+/-" at 13774,5262 h60
  text "HOLE SIZE TOLERANCE (UNLESS OTHERWISE SPECIFIED):" at 11404.23,5257 h60
  text "3" at 14013.2,5257 h60
  text "MIL" at 14129.46,5257 h60
  text "MATERIAL:" at 11329.46,5047.54 h60
  text "FR-4 High Tg" at 12315.9,4907.21 h60
  text "FR-408" at 11750.46,4898.64 h60
  text "OTHER" at 13238.46,4898.64 h60
  text "X" at 12161,4895 h60
  text "62 MIL (1.6mm) +/-10%" at 12070.56,4735.92 h60
  text "THICKNESS:" at 11404.23,4731.64 h60
  text "X" at 11942.4,4731.64 h60
  text "OTHER" at 13355.46,4731.64 h60
  text "TOLERANCE:" at 11404.23,4573.64 h60
  text "X" at 12243.53,4573.64 h60
  text "ANSI IPC-6012 TYPE 3 CLASS 2" at 12430.48,4573.64 h60
  text "OTHER +/-" at 12430.46,4417.64 h60
  text "BOW & TWIST:" at 11404.23,4260.64 h60
  text "X" at 12243.53,4260.64 h60
  text "ANSI IPC-6012 TYPE 3 CLASS 2" at 12430.48,4260.64 h60
  text "OTHER +/-" at 12430.46,4102.13 h60
  text "DRILLING:" at 11329.46,3963.64 h60
  text "REFERENCE:" at 11404.23,3846.64 h60
  text "X" at 12052.46,3846.64 h60
  text "AS SHOWN" at 12239.46,3846.64 h60
  text "X" at 12953.46,3846.64 h60
  text "NC_DRILL FILES" at 13090.46,3846.64 h60
  text "PTH COPPER THICKNESS:" at 11404.23,3688.64 h60
  text "X" at 12534.46,3688.64 h60
  text "20-30 um" at 12671.46,3688.64 h60
  text "OTHER" at 13388.46,3688.64 h60
  text "BOARD FINISH:" at 11329.46,3529.64 h60
  text "SILKSCREEN:" at 11484.68,3411.64 h60
  text "X" at 12433.46,3411.64 h60
  text "TOP" at 12559.46,3411.64 h60
  text "BOTTOM" at 13070.46,3411.64 h60
  text "SILKSCREEN COLOR:" at 11484.68,3244.64 h60
  text "X" at 12432.42,3244.64 h60
  text "WHITE" at 12559.46,3244.64 h60
  text "OTHER" at 13070.46,3244.64 h60
  text "X" at 12563.42,3085.44 h60
  text "GREEN" at 12690.46,3085.44 h60
  text "OTHER" at 13308.46,3085.44 h60
  text "SOLDER RESIST COLOR:" at 11484.68,3074.64 h60
  text "X" at 12563.42,2915.44 h60
  text "MATTE" at 12690.46,2915.44 h60
  text "SEMI-GLOSS" at 13308,2914.8 h60
  text "IMMERSION GOLD (ENIG)" at 12390.46,2726.92 h60
  text "ENEPIG" at 13728,2723.64 h60
  text "SURFACE FINISH:" at 11329.46,2722.64 h60
  text "X" at 12203.51,2722.64 h60
  text "IMM. TIN/SILVER OR EQUIV" at 11659,2565.64 h60
  text "OTHER" at 13090.46,2565.64 h60
  text "ARRAY/PANEL:" at 11329.46,2386.64 h60
  text "CUT AND TRIM PER M1 BOARD OUTLINE" at 12390.46,2382.35 h60
  text "N.C. ROUTE" at 12390.46,2230.64 h60
  text "X" at 13069.46,2230.64 h60
  text "V. SCORE" at 13256.46,2230.64 h60
  text "CERTIFICATION:" at 11329.46,2093.64 h60
  text "MATERIALS AND WORKMANSHIP FOR ALL PCBS" at 12054.46,2093.64 h60
  text "TO MEET OR EXCEED THE REQUIREMENTS OF:" at 12054.46,1995.64 h60
  text "X" at 11680.96,1859.13 h60
  text "ANSI IPC-A-600F CLASS ->" at 11819.96,1859.13 h60
  text "X" at 13459.02,1859.13 h60
  text "2" at 13577.96,1859.14 h60
  text "1" at 13262.96,1857.64 h60
  text "3" at 13931.96,1857.64 h60
  text "X" at 12495.02,1699.64 h60
  text "RoHS" at 12631.96,1699.64 h60
  text "OTHER" at 13276.36,1699.64 h60
  text "PER ORDER" at 13673.42,1699.64 h60
  text "ALL BOARDS MUST MEET OR EXCEED UL94-V0 REQUIREMENTS." at 11357,1534 h60
  text "PCB MUST BEAR THE UL94V-0 UL REGISTERED MATERIAL ID NUMBER" at 11357,1414 h60
  text "IMPEDANCE:" at 12597,1285 h60
  text "YES" at 13251.46,1278.92 h60
  text "X" at 13514.05,1278 h60
  text "NO" at 13676,1277.64 h60
  text "ADDITIONAL REQUIREMENTS:" at 11329.46,1240.64 h60
  text "MICROSECTION:" at 11404.23,1125.64 h60
  text "YES" at 12309.96,1125.64 h60
  text "YES" at 13249.46,1124.92 h60
  text "VIATENTED:" at 12584,1124 h60
  text "X" at 13512.05,1124 h60
  text "NO" at 13674,1123.64 h60
  text "REQUIRED" at 13171.46,969.49 h60
  text "BARE BOARD ELEC. TEST:" at 11404.23,966.64 h60
  text "NONE" at 12709.96,966.64 h60
  text "X" at 13044.46,966.64 h60
  text "PER ORDER" at 13763.46,966.64 h60
M11 Gerber Information:
  lines w10: -292,-930.17 6308,-930.17 ; -292,-726.83 6310,-726.83 ; -292,-523.5 -292,-1133.5 3713,-1133.5 6310,-1133.5 6310,-523.5 -291.5,-523.5 -291.5,-1133.5 1284,-1133.5 ; 2173,-1133.5 2173,-523.5 ; 3440,-726.83 3440,-523.5 ; 4280,-726.83 4280,-523.5 ; 4902,-1140 4902,-937.17
  text "ALL ARTWORK VIEWED FROM TOP SIDE" at -228.5,-655.67 h60
  text "BOARD #:" at 2248,-655.67 h60
  text ".PRJ_Number" at 2793.5,-655.67 h60
  text "REV:" at 3638,-655.67 h60
  text ".PCB_Rev" at 3929.5,-655.67 h60
  text "SVN REV:" at 4476,-655.67 h60
  text ".VersionControl_RevNumber" at 4982,-655.67 h60
  text "LAYER NAME =" at -228.5,-858.49 h60
  text "TID #:" at 2248,-859 h60
  text ".TID" at 2793.5,-859 h60
  text "PLOT NAME =" at -228.5,-1064.34 h60
  text ".plot_File_Name" at 577,-1064.34 h60
  text "GENERATED    :" at 2250,-1064.34 h60
  text ".Print_Date" at 3119.5,-1064.34 h60
  text ".Print_Time" at 3848.5,-1064.34 h60
  text "TEXAS INSTRUMENTS" at 5113,-1064.34 h60
M12 Stackup:
  drawing of 295 lines, arcs and shapes, not listed
  text "Layer" at 9752.58,7777.37 h60
  text "Name" at 10162.49,7777.37 h60
  text "Material" at 11102.23,7777.37 h60
  text "Thickness" at 11962,7777.37 h60
  text "Constant" at 12611.84,7777.37 h60
  text "Board Layer Stack" at 13181.7,7777.37 h60
  text "1" at 9752.58,7657.37 h60
  text "Top Overlay" at 10162.49,7657.37 h60
  text "2" at 9752.58,7537.37 h60
  text "Top Solder" at 10162.49,7537.37 h60
  text "Solder Resist" at 11102.23,7537.37 h60
  text "0.40mil" at 11962,7537.37 h60
  text "3.5" at 12611.84,7537.37 h60
  text "3" at 9752.58,7417.37 h60
  text "Top Layer" at 10162.49,7417.37 h60
  text "Copper" at 11102.23,7417.37 h60
  text "1.40mil" at 11962,7417.37 h60
  text "4" at 9752.58,7297.37 h60
  text "Dielectric 1" at 10162.49,7297.37 h60
  text "FR-4 High Tg" at 11102.23,7297.37 h60
  text "8.00mil" at 11962,7297.37 h60
  text "4.2" at 12611.84,7297.37 h60
  text "5" at 9752.58,7177.37 h60
  text "Signal Layer 1" at 10162.49,7177.37 h60
  text "Copper" at 11102.23,7177.37 h60
  text "1.40mil" at 11962,7177.37 h60
  text "6" at 9752.58,7057.37 h60
  text "Dielectric 2" at 10162.49,7057.37 h60
  text "FR-4 High Tg" at 11102.23,7057.37 h60
  text "40.00mil" at 11962,7057.37 h60
  text "4.2" at 12611.84,7057.37 h60
  text "7" at 9752.58,6937.37 h60
  text "Signal Layer 2" at 10162.49,6937.37 h60
  text "Copper" at 11102.23,6937.37 h60
  text "1.40mil" at 11962,6937.37 h60
  text "8" at 9752.58,6817.37 h60
  text "Dielectric 3" at 10162.49,6817.37 h60
  text "FR-4 High Tg" at 11102.23,6817.37 h60
  text "8.00mil" at 11962,6817.37 h60
  text "4.2" at 12611.84,6817.37 h60
  text "9" at 9752.58,6697.37 h60
  text "Bottom Layer" at 10162.49,6697.37 h60
  text "Copper" at 11102.23,6697.37 h60
  text "1.40mil" at 11962,6697.37 h60
  text "10" at 9752.58,6577.37 h60
  text "Bottom Solder" at 10162.49,6577.37 h60
  text "Solder Resist" at 11102.23,6577.37 h60
  text "0.40mil" at 11962,6577.37 h60
  text "3.5" at 12611.84,6577.37 h60
  text "11" at 9752.58,6457.37 h60
  text "Bottom Overlay" at 10162.49,6457.37 h60
M13 Component Bodies Top:
  text ".Layer_Name" at 577,-858.49 h60
M14 Component Bodies Bottom:
  text ".Layer_Name" at 577,-858.49 h60
M15 Courtyards Top:
  text ".Layer_Name" at 577,-858.49 h60
M16 Courtyards Bottom:
  text ".Layer_Name" at 577,-858.49 h60
Drill Drawing:
  circle w15: c4852.19,4251.94 r26.67
  circle w15: c4852.19,4251.94 r44.44
  circle w15: c4852.19,1851.94 r44.44
  lines w15: 4727.5,1547.5 8920.18,1547.5 ; 4727.5,4547.5 8920.18,4547.5 ; 5402.95,1347.5 5402.95,4747.5 ; 6185.67,1347.5 6185.67,4747.5 ; 7534.68,1347.5 7534.68,4747.5 ; 8069.23,1347.5 8069.23,4747.5 ; 4727.5,1347.5 8920.18,1347.5 8920.18,4747.5 4727.5,4747.5 4727.5,1347.5 ; 4807.74,1696.39 4896.63,1696.39 4852.19,1607.5 4807.74,1696.39 ; 4807.74,2007.5 4852.19,2029.72 4896.63,2007.5 4874.41,2051.94 4896.63,2096.39 4852.19,2074.17 4807.74,2096.39 4829.97,2051.94 4807.74,2007.5 ; 4807.74,2207.5 4896.63,2207.5 4896.63,2296.39 4807.74,2296.39 4807.74,2207.5 ; 4807.74,2451.94 4852.19,2407.5 4896.63,2451.94 4852.19,2496.39 4807.74,2451.94 ; 4807.74,3029.72 4829.97,3029.72 4829.97,3007.5 4874.41,3007.5 4874.41,3029.72 4896.63,3029.72 4896.63,3074.17 4874.41,3074.17 4874.41,3096.39 4829.97,3096.39 4829.97,3074.17 4807.74,3074.17 4807.74,3029.72 ; 4807.74,3229.72 4829.97,3229.72 4852.19,3207.5 4874.41,3229.72 4896.63,3229.72 4874.41,3251.94 4896.63,3274.17 4874.41,3274.17 4852.19,3296.39 4829.97,3274.17 4807.74,3274.17 4829.97,3251.94 4807.74,3229.72 ; 4807.74,3407.5 4807.74,3429.72 4829.97,3451.94 4807.74,3474.17 4807.74,3496.39 4829.97,3496.39 4852.19,3474.17 4874.41,3496.39 4896.63,3496.39 4896.63,3474.17 4874.41,3451.94 4896.63,3429.72 4896.63,3407.5 4874.41,3407.5 4852.19,3429.72 4829.97,3407.5 4807.74,3407.5 ; 4807.74,3629.72 4829.97,3629.72 4829.97,3607.5 4874.41,3607.5 4874.41,3629.72 4896.63,3629.72 4896.63,3674.17 4874.41,3674.17 4874.41,3696.39 4829.97,3696.39 4829.97,3674.17 4807.74,3674.17 4807.74,3629.72 ; 4807.74,3807.5 4807.74,3829.72 4829.97,3851.94 4807.74,3874.17 4807.74,3896.39 4829.97,3896.39 4852.19,3874.17 4874.41,3896.39 4896.63,3896.39 4896.63,3874.17 4874.41,3851.94 4896.63,3829.72 4896.63,3807.5 4874.41,3807.5 4852.19,3829.72 4829.97,3807.5 4807.74,3807.5 ; 4807.74,4496.39 4896.63,4496.39 4852.19,4407.5 4807.74,4496.39 ; 4825.52,3238.61 4838.85,3238.61 4852.19,3225.28 4865.52,3238.61 4878.85,3238.61 4865.52,3251.94 4878.85,3265.28 4865.52,3265.28 4852.19,3278.61 4838.85,3265.28 4825.52,3265.28 4838.85,3251.94 4825.52,3238.61 ; 4825.52,3638.61 4838.85,3638.61 4838.85,3625.28 4865.52,3625.28 4865.52,3638.61 4878.85,3638.61 4878.85,3665.28 4865.52,3665.28 4865.52,3678.61 4838.85,3678.61 4838.85,3665.28 4825.52,3665.28 4825.52,3638.61 ; 4825.52,3825.28 4825.52,3838.61 4838.85,3851.94 4825.52,3865.28 4825.52,3878.61 4838.85,3878.61 4852.19,3865.28 4865.52,3878.61 4878.85,3878.61 4878.85,3865.28 4865.52,3851.94 4878.85,3838.61 4878.85,3825.28 4865.52,3825.28 4852.19,3838.61 4838.85,3825.28 4825.52,3825.28 ; 4825.52,4478.61 4878.85,4478.61 4852.19,4425.28 4825.52,4478.61
  text "NOTE: VIAS IN PAD (VP) TO BE FILLED WITH CONDUCTIVE MATERIAL" at 4762,4956 h80
  text "DRILL TABLE" at 4767,4827 h80
  text "Symbol" at 4847.5,4607.5 h96
  text "Hit Count" at 5462.95,4607.5 h96
  text "Finished Hole Size" at 6245.67,4607.5 h96
  text "Plated" at 7594.68,4607.5 h96
  text "Hole Type" at 8129.23,4607.5 h96
  text "153" at 5462.95,4407.5 h80
  text "6.00mil (0.152mm)" at 6245.67,4407.5 h80
  text "PTH" at 7594.68,4407.5 h80
  text "Round" at 8129.23,4407.5 h80
  text "21" at 5462.95,4207.5 h80
  text "7.87mil (0.200mm)" at 6245.67,4207.5 h80
  text "PTH" at 7594.68,4207.5 h80
  text "Round" at 8129.23,4207.5 h80
  text "4" at 5462.95,4007.5 h80
  text "8.00mil (0.203mm)" at 6245.67,4007.5 h80
  text "PTH" at 7594.68,4007.5 h80
  text "Round" at 8129.23,4007.5 h80
  text "C" at 4807.57,3992.51 h88.89
  text "2" at 5462.95,3807.5 h80
  text "10.00mil (0.254mm)" at 6245.67,3807.5 h80
  text "PTH" at 7594.68,3807.5 h80
  text "Round" at 8129.23,3807.5 h80
  text "10" at 5462.95,3607.5 h80
  text "16.00mil (0.406mm)" at 6245.67,3607.5 h80
  text "PTH" at 7594.68,3607.5 h80
  text "Round" at 8129.23,3607.5 h80
  text "8" at 5462.95,3407.5 h80
  text "18.00mil (0.457mm)" at 6245.67,3407.5 h80
  text "PTH" at 7594.68,3407.5 h80
  text "Round" at 8129.23,3407.5 h80
  text "35" at 5462.95,3207.5 h80
  text "20.00mil (0.508mm)" at 6245.67,3207.5 h80
  text "PTH" at 7594.68,3207.5 h80
  text "Round" at 8129.23,3207.5 h80
  text "24" at 5462.95,3007.5 h80
  text "27.56mil (0.700mm)" at 6245.67,3007.5 h80
  text "PTH" at 7594.68,3007.5 h80
  text "Round" at 8129.23,3007.5 h80
  text "2" at 5462.95,2807.5 h80
  text "28.00mil (0.711mm)" at 6245.67,2807.5 h80
  text "PTH" at 7594.68,2807.5 h80
  text "Round" at 8129.23,2807.5 h80
  text "B" at 4807.57,2792.51 h88.89
  text "2" at 5462.95,2607.5 h80
  text "30.00mil (0.762mm)" at 6245.67,2607.5 h80
  text "PTH" at 7594.68,2607.5 h80
  text "Round" at 8129.23,2607.5 h80
  text "A" at 4807.57,2592.51 h88.89
  text "4" at 5462.95,2407.5 h80
  text "39.37mil (1.000mm)" at 6245.67,2407.5 h80
  text "PTH" at 7594.68,2407.5 h80
  text "Round" at 8129.23,2407.5 h80
  text "13" at 5462.95,2207.5 h80
  text "40.00mil (1.016mm)" at 6245.67,2207.5 h80
  text "PTH" at 7594.68,2207.5 h80
  text "Round" at 8129.23,2207.5 h80
  text "2" at 5462.95,2007.5 h80
  text "45.28mil (1.150mm)" at 6245.67,2007.5 h80
  text "NPTH" at 7594.68,2007.5 h80
  text "Round" at 8129.23,2007.5 h80
  text "4" at 5462.95,1807.5 h80
  text "125.98mil (3.200mm)" at 6245.67,1807.5 h80
  text "PTH" at 7594.68,1807.5 h80
  text "Round" at 8129.23,1807.5 h80
  text "4" at 5462.95,1607.5 h80
  text "236.22mil (6.000mm)" at 6245.67,1607.5 h80
  text "PTH" at 7594.68,1607.5 h80
  text "Round" at 8129.23,1607.5 h80
  text "288 Total" at 5462.95,1407.5 h80
  text "FOR 6MIL DRILL +0/-6MIL" at 4975,1192 h80
  text "FOR 7.87MIL DRILL +0/-7.87MIL" at 4975,1097 h80
  text "FOR 8MIL DRILL +0/-8MIL" at 4975,1009 h80
  text "FOR 10MIL DRILL +0/-10MIL" at 4975,929 h80
  text "FOR 16MIL DRILL +0/-16MIL" at 4975,837 h80
  text "FOR 18MIL DRILL +0/-18MIL" at 4975,753 h80
  text "FOR PTH DRILL +/-3MIL" at 4975,669 h80
  text "FOR NPTH DRILL +/-2MIL" at 4969,583 h80
  text ".Layer_Name" at 582,-848.49 h60
Mechanical 17:
  text ".Layer_Name" at 577,-858.49 h60
Mechanical 18:
  text ".Layer_Name" at 577,-858.49 h60
Mechanical 19:
  text ".Layer_Name" at 577,-858.49 h60

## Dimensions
0,3450 to 4150,3450 on M2 Board Dimensions
0,0 to 0,3450 on M2 Board Dimensions
0,-400 to 1000,-400 on M2 Board Dimensions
